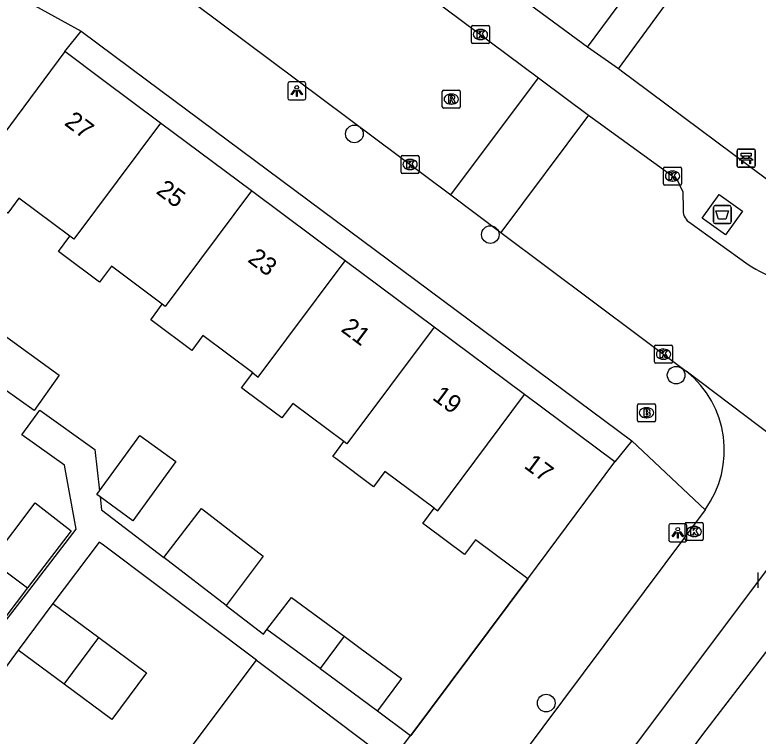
# Model space of a CAD drawing. Extents: x 160026 to 161302, y 384757 to 385701.
# Drawn here: x 160351.49 to 160392.73, y 385213.57 to 385253.6 of the extents above; entities that cross this region are included whole.
import ezdxf

# ---------------------------------------------------------------- set-up
doc = ezdxf.new("R2010")
doc.units = 0
for name, color, linetype in [('IMGEO_Afval_apart_plaats', 7, 'Continuous'), ('IMGEO_Bank', 7, 'Continuous'), ('IMGEO_Boom', 7, 'Continuous'), ('IMGEO_Brandkraan', 7, 'Continuous'), ('IMGEO_Kolk', 7, 'Continuous'), ('IMGEO_Lichtpunt', 7, 'Continuous'), ('IMGEO_Muur', 7, 'Continuous'), ('IMGEO_Pand', 7, 'Continuous'), ('IMGEO_Pand_nummerreeks', 7, 'Continuous'), ('IMGEO_Rijbaan_lokaal_gesloten', 7, 'Continuous'), ('IMGEO_Rijbaan_lokaal_open', 7, 'Continuous'), ('IMGEO_Rioolput', 7, 'Continuous'), ('IMGEO_Voetpad_gesloten', 7, 'Continuous'), ('IMGEO_Voetpad_open', 7, 'Continuous')]:
    doc.layers.add(name, color=color, linetype=linetype)

msp = doc.modelspace()

# ---------------------------------------------------------------- linework, layer by layer
at = {"layer": 'IMGEO_Afval_apart_plaats'}
for p, q in [((160390.249, 385242.11), (160390.249, 385242.91)), ((160390.249, 385242.91), (160390.249, 385242.11)), ((160390.349, 385243.01), (160391.139, 385243.01)), ((160391.139, 385243.01), (160390.349, 385243.01)), ((160391.239, 385242.91), (160391.239, 385242.11)), ((160391.239, 385242.11), (160391.239, 385242.91)), ((160391.139, 385242.01), (160390.349, 385242.01)), ((160390.349, 385242.01), (160391.139, 385242.01))]:
    msp.add_line(p, q, dxfattribs=at)
msp.add_lwpolyline([(160390.392, 385242.724), (160391.096, 385242.724), (160390.947, 385242.254), (160390.541, 385242.254), (160390.392, 385242.724)], dxfattribs=at)
for centre, start, end in [((160390.349, 385242.91), 90, 180), ((160390.349, 385242.91), 90, 180), ((160391.139, 385242.91), 0, 90), ((160391.139, 385242.91), 360, 90), ((160390.349, 385242.11), 180, 270), ((160390.349, 385242.11), 180, 270), ((160391.139, 385242.11), 270, 0), ((160391.139, 385242.11), 270, 0)]:
    msp.add_arc(centre, 0.1, start, end, dxfattribs=at)
at = {"layer": 'IMGEO_Bank'}
for p, q in [((160391.645, 385246.144), (160392.486, 385246.144)), ((160392.486, 385246.144), (160391.645, 385246.144)), ((160391.57, 385245.219), (160391.57, 385246.06)), ((160391.57, 385246.06), (160391.57, 385245.219)), ((160391.879, 385245.65), (160391.879, 385245.756)), ((160391.923, 385245.756), (160391.923, 385245.65)), ((160392.211, 385245.762), (160391.929, 385245.762)), ((160392.217, 385245.65), (160392.217, 385245.756)), ((160392.261, 385245.756), (160392.261, 385245.65)), ((160392.57, 385246.069), (160392.57, 385245.228)), ((160392.57, 385245.228), (160392.57, 385246.069)), ((160392.267, 385245.542), (160391.874, 385245.542)), ((160391.929, 385245.644), (160392.211, 385245.644)), ((160392.495, 385245.144), (160391.654, 385245.144)), ((160391.654, 385245.144), (160392.495, 385245.144))]:
    msp.add_line(p, q, dxfattribs=at)
for points in [[(160391.873, 385245.762), (160391.787, 385245.762), (160391.787, 385245.923), (160392.35, 385245.923), (160392.35, 385245.762), (160392.267, 385245.762)], [(160391.817, 385245.542), (160391.675, 385245.542), (160391.787, 385245.644), (160391.873, 385245.644)], [(160391.867, 385245.535), (160391.867, 385245.328), (160391.824, 385245.328), (160391.824, 385245.535)], [(160392.267, 385245.644), (160392.35, 385245.644), (160392.462, 385245.542), (160392.323, 385245.542)], [(160392.317, 385245.535), (160392.317, 385245.328), (160392.273, 385245.328), (160392.273, 385245.535)]]:
    msp.add_lwpolyline(points, dxfattribs=at)
for centre, radius, start, end in [((160391.648, 385246.066), 0.0779, 92.4484, 184.2845), ((160391.648, 385246.066), 0.0779, 92.4484, 184.2845), ((160392.492, 385246.066), 0.0779, 2.4484, 94.2845), ((160392.492, 385246.066), 0.0779, 2.4484, 94.2845), ((160391.872, 385245.755), 0.00671, 2.8957, 87.1043), ((160391.929, 385245.755), 0.00671, 92.8957, 177.1043), ((160392.211, 385245.755), 0.00671, 2.8957, 87.1043), ((160392.268, 385245.755), 0.00671, 92.8957, 177.1043), ((160391.817, 385245.535), 0.00671, 2.8957, 87.1043), ((160391.874, 385245.535), 0.00671, 92.8957, 177.1043), ((160391.872, 385245.651), 0.00671, 272.8957, 357.1043), ((160391.929, 385245.651), 0.00671, 182.8957, 267.1043), ((160392.211, 385245.651), 0.00671, 272.8957, 357.1043), ((160392.268, 385245.651), 0.00671, 182.8957, 267.1043), ((160392.266, 385245.535), 0.00671, 2.8957, 87.1043), ((160392.323, 385245.535), 0.00671, 92.8957, 177.1043), ((160391.648, 385245.222), 0.0779, 182.4484, 274.2845), ((160391.648, 385245.222), 0.0779, 182.4484, 274.2845), ((160392.492, 385245.222), 0.0779, 272.4484, 4.2845), ((160392.492, 385245.222), 0.0779, 272.4484, 4.2845)]:
    msp.add_arc(centre, radius, start, end, dxfattribs=at)
at = {"layer": 'IMGEO_Boom'}
for centre in [(160370.33, 385246.99), (160377.873, 385241.404), (160388.183, 385233.601), (160380.975, 385215.404)]:
    msp.add_circle(centre, 0.489, dxfattribs=at)
at = {"layer": 'IMGEO_Brandkraan'}
for p, q in [((160386.039, 385231.09), (160386.039, 385231.942)), ((160386.114, 385232.016), (160386.966, 385232.016)), ((160386.527, 385231.796), (160386.552, 385231.796)), ((160387.04, 385231.942), (160387.04, 385231.09)), ((160386.966, 385231.016), (160386.114, 385231.016)), ((160386.55, 385231.236), (160386.525, 385231.236))]:
    msp.add_line(p, q, dxfattribs=at)
for points in [[(160386.039, 385231.09), (160386.039, 385231.942)], [(160386.114, 385232.016), (160386.966, 385232.016)], [(160386.387, 385231.716), (160386.387, 385231.316), (160386.6, 385231.316)], [(160386.618, 385231.716), (160386.387, 385231.716)], [(160387.04, 385231.942), (160387.04, 385231.09)], [(160386.566, 385231.635), (160386.512, 385231.635), (160386.512, 385231.559)], [(160386.512, 385231.559), (160386.565, 385231.559)], [(160386.574, 385231.483), (160386.512, 385231.483), (160386.512, 385231.402)], [(160386.512, 385231.402), (160386.574, 385231.402)], [(160386.966, 385231.016), (160386.114, 385231.016)]]:
    msp.add_lwpolyline(points, dxfattribs=at)
for centre, radius, start, end in [((160386.116, 385231.94), 0.0765, 91.552, 178.448), ((160386.116, 385231.94), 0.0765, 91.552, 178.448), ((160386.622, 385231.571), 0.145, 59.4692, 91.5367), ((160386.647, 385231.618), 0.0922, 285.5137, 58.1501), ((160386.964, 385231.94), 0.0765, 1.552, 88.448), ((160386.964, 385231.94), 0.0765, 1.552, 88.448), ((160386.567, 385231.597), 0.0379, 267.8285, 90.9355), ((160386.575, 385231.442), 0.0404, 269.8759, 90.5077), ((160386.606, 385231.567), 0.251, 268.6676, 293.5347), ((160386.652, 385231.426), 0.105, 301.3115, 78.989), ((160386.116, 385231.092), 0.0765, 181.552, 268.448), ((160386.116, 385231.092), 0.0765, 181.552, 268.448), ((160386.964, 385231.092), 0.0765, 271.552, 358.448), ((160386.964, 385231.092), 0.0765, 271.552, 358.448)]:
    msp.add_arc(centre, radius, start, end, dxfattribs=at)
for centre, major_axis, ratio, start_param, end_param in [((160386.526, 385231.516), (-0.387, 0.002), 0.722429, 4.712389, 7.853982), ((160386.551, 385231.516), (-0.39, 0.002), 0.717154, 1.570796, 4.712389)]:
    msp.add_ellipse(centre, major_axis=major_axis, ratio=ratio, start_param=start_param, end_param=end_param, dxfattribs=at)
at = {"layer": 'IMGEO_Kolk'}
for p, q in [((160376.824, 385252.082), (160376.824, 385252.934)), ((160376.899, 385253.008), (160377.751, 385253.008)), ((160377.312, 385252.788), (160377.337, 385252.788)), ((160377.825, 385252.934), (160377.825, 385252.082)), ((160377.751, 385252.008), (160376.899, 385252.008)), ((160377.335, 385252.228), (160377.31, 385252.228)), ((160372.918, 385244.868), (160372.918, 385245.72)), ((160372.993, 385245.794), (160373.845, 385245.794)), ((160373.919, 385245.72), (160373.919, 385244.868)), ((160373.406, 385245.574), (160373.431, 385245.574)), ((160373.429, 385245.014), (160373.404, 385245.014)), ((160387.485, 385244.223), (160387.485, 385245.075)), ((160387.56, 385245.149), (160388.412, 385245.149)), ((160387.973, 385244.929), (160387.998, 385244.929)), ((160388.486, 385245.075), (160388.486, 385244.223)), ((160373.845, 385244.794), (160372.993, 385244.794)), ((160388.412, 385244.149), (160387.56, 385244.149)), ((160387.996, 385244.369), (160387.971, 385244.369)), ((160386.985, 385234.339), (160386.985, 385235.191)), ((160387.06, 385235.265), (160387.912, 385235.265)), ((160387.473, 385235.045), (160387.498, 385235.045)), ((160387.986, 385235.191), (160387.986, 385234.339)), ((160387.912, 385234.265), (160387.06, 385234.265)), ((160387.496, 385234.485), (160387.471, 385234.485)), ((160388.684, 385224.499), (160388.684, 385225.351)), ((160388.759, 385225.425), (160389.611, 385225.425)), ((160389.172, 385225.205), (160389.197, 385225.205)), ((160389.685, 385225.351), (160389.685, 385224.499)), ((160389.195, 385224.645), (160389.17, 385224.645)), ((160389.611, 385224.425), (160388.759, 385224.425)), ((160392.733, 385221.805), (160392.733, 385222.657))]:
    msp.add_line(p, q, dxfattribs=at)
for points in [[(160376.824, 385252.082), (160376.824, 385252.934)], [(160376.899, 385253.008), (160377.751, 385253.008)], [(160377.145, 385252.708), (160377.268, 385252.708), (160377.268, 385252.557), (160377.398, 385252.708), (160377.562, 385252.708), (160377.416, 385252.557), (160377.569, 385252.308), (160377.417, 385252.308), (160377.332, 385252.472), (160377.268, 385252.405), (160377.268, 385252.308), (160377.145, 385252.308), (160377.145, 385252.708)], [(160377.825, 385252.934), (160377.825, 385252.082)], [(160377.751, 385252.008), (160376.899, 385252.008)], [(160372.918, 385244.868), (160372.918, 385245.72)], [(160372.993, 385245.794), (160373.845, 385245.794)], [(160373.919, 385245.72), (160373.919, 385244.868)], [(160373.239, 385245.494), (160373.362, 385245.494), (160373.362, 385245.343), (160373.492, 385245.494), (160373.656, 385245.494), (160373.51, 385245.343), (160373.663, 385245.094), (160373.511, 385245.094), (160373.426, 385245.258), (160373.362, 385245.191), (160373.362, 385245.094), (160373.239, 385245.094), (160373.239, 385245.494)], [(160387.485, 385244.223), (160387.485, 385245.075)], [(160387.56, 385245.149), (160388.412, 385245.149)], [(160387.806, 385244.849), (160387.929, 385244.849), (160387.929, 385244.698), (160388.059, 385244.849), (160388.223, 385244.849), (160388.077, 385244.698), (160388.23, 385244.449), (160388.078, 385244.449), (160387.993, 385244.613), (160387.929, 385244.546), (160387.929, 385244.449), (160387.806, 385244.449), (160387.806, 385244.849)], [(160388.486, 385245.075), (160388.486, 385244.223)], [(160373.845, 385244.794), (160372.993, 385244.794)], [(160388.412, 385244.149), (160387.56, 385244.149)], [(160386.985, 385234.339), (160386.985, 385235.191)], [(160387.06, 385235.265), (160387.912, 385235.265)], [(160387.306, 385234.965), (160387.429, 385234.965), (160387.429, 385234.814), (160387.559, 385234.965), (160387.723, 385234.965), (160387.577, 385234.814), (160387.73, 385234.565), (160387.578, 385234.565), (160387.493, 385234.729), (160387.429, 385234.662), (160387.429, 385234.565), (160387.306, 385234.565), (160387.306, 385234.965)], [(160387.986, 385235.191), (160387.986, 385234.339)], [(160387.912, 385234.265), (160387.06, 385234.265)], [(160388.684, 385224.499), (160388.684, 385225.351)], [(160388.759, 385225.425), (160389.611, 385225.425)], [(160389.005, 385225.125), (160389.128, 385225.125), (160389.128, 385224.974), (160389.258, 385225.125), (160389.422, 385225.125), (160389.276, 385224.974), (160389.429, 385224.725), (160389.277, 385224.725), (160389.192, 385224.889), (160389.128, 385224.822), (160389.128, 385224.725), (160389.005, 385224.725), (160389.005, 385225.125)], [(160389.685, 385225.351), (160389.685, 385224.499)], [(160389.611, 385224.425), (160388.759, 385224.425)], [(160392.733, 385221.805), (160392.733, 385222.657)]]:
    msp.add_lwpolyline(points, dxfattribs=at)
for centre, start, end in [((160376.901, 385252.932), 91.552, 178.448), ((160376.901, 385252.932), 91.552, 178.448), ((160377.749, 385252.932), 1.552, 88.448), ((160377.749, 385252.932), 1.552, 88.448), ((160376.901, 385252.084), 181.552, 268.448), ((160376.901, 385252.084), 181.552, 268.448), ((160377.749, 385252.084), 271.552, 358.448), ((160377.749, 385252.084), 271.552, 358.448), ((160372.995, 385245.718), 91.552, 178.448), ((160372.995, 385245.718), 91.552, 178.448), ((160373.843, 385245.718), 1.552, 88.448), ((160373.843, 385245.718), 1.552, 88.448), ((160372.995, 385244.87), 181.552, 268.448), ((160372.995, 385244.87), 181.552, 268.448), ((160373.843, 385244.87), 271.552, 358.448), ((160373.843, 385244.87), 271.552, 358.448), ((160387.562, 385245.073), 91.552, 178.448), ((160387.562, 385245.073), 91.552, 178.448), ((160388.41, 385245.073), 1.552, 88.448), ((160388.41, 385245.073), 1.552, 88.448), ((160387.562, 385244.225), 181.552, 268.448), ((160387.562, 385244.225), 181.552, 268.448), ((160388.41, 385244.225), 271.552, 358.448), ((160388.41, 385244.225), 271.552, 358.448), ((160387.062, 385235.189), 91.552, 178.448), ((160387.062, 385235.189), 91.552, 178.448), ((160387.91, 385235.189), 1.552, 88.448), ((160387.91, 385235.189), 1.552, 88.448), ((160387.062, 385234.341), 181.552, 268.448), ((160387.062, 385234.341), 181.552, 268.448), ((160387.91, 385234.341), 271.552, 358.448), ((160387.91, 385234.341), 271.552, 358.448), ((160388.761, 385225.349), 91.552, 178.448), ((160388.761, 385225.349), 91.552, 178.448), ((160389.609, 385225.349), 1.552, 88.448), ((160389.609, 385225.349), 1.552, 88.448), ((160388.761, 385224.501), 181.552, 268.448), ((160388.761, 385224.501), 181.552, 268.448), ((160389.609, 385224.501), 271.552, 358.448), ((160389.609, 385224.501), 271.552, 358.448)]:
    msp.add_arc(centre, 0.0765, start, end, dxfattribs=at)
for centre, major_axis, ratio, start_param, end_param in [((160377.311, 385252.508), (-0.387, 0.002), 0.722429, 4.712389, 7.853982), ((160377.336, 385252.508), (-0.39, 0.002), 0.717154, 1.570796, 4.712389), ((160373.405, 385245.294), (-0.387, 0.002), 0.722429, 4.712389, 7.853982), ((160373.43, 385245.294), (-0.39, 0.002), 0.717154, 1.570796, 4.712389), ((160387.972, 385244.649), (-0.387, 0.002), 0.722429, 4.712389, 7.853982), ((160387.997, 385244.649), (-0.39, 0.002), 0.717154, 1.570796, 4.712389), ((160387.472, 385234.765), (-0.387, 0.002), 0.722429, 4.712389, 7.853982), ((160387.497, 385234.765), (-0.39, 0.002), 0.717154, 1.570796, 4.712389), ((160389.171, 385224.925), (-0.387, 0.002), 0.722429, 4.712389, 7.853982), ((160389.196, 385224.925), (-0.39, 0.002), 0.717154, 1.570796, 4.712389)]:
    msp.add_ellipse(centre, major_axis=major_axis, ratio=ratio, start_param=start_param, end_param=end_param, dxfattribs=at)
at = {"layer": 'IMGEO_Lichtpunt'}
for p, q in [((160367.538, 385249.872), (160366.73, 385249.872)), ((160367.538, 385249.872), (160366.73, 385249.872)), ((160366.636, 385249.777), (160366.636, 385248.97)), ((160366.636, 385249.777), (160366.636, 385248.97)), ((160367.632, 385248.97), (160367.632, 385249.777)), ((160367.632, 385248.97), (160367.632, 385249.777)), ((160366.73, 385248.876), (160367.538, 385248.876)), ((160366.73, 385248.876), (160367.538, 385248.876)), ((160387.776, 385225.258), (160387.776, 385224.451)), ((160387.776, 385225.258), (160387.776, 385224.451)), ((160388.678, 385225.353), (160387.87, 385225.353)), ((160388.678, 385225.353), (160387.87, 385225.353)), ((160388.772, 385224.451), (160388.772, 385225.258)), ((160388.772, 385224.451), (160388.772, 385225.258)), ((160387.87, 385224.357), (160388.678, 385224.357)), ((160387.87, 385224.357), (160388.678, 385224.357))]:
    msp.add_line(p, q, dxfattribs=at)
for points in [[(160367.01, 385249.441), (160367.049, 385249.413), (160366.861, 385249.151), (160366.823, 385249.178), (160367.01, 385249.441)], [(160367.112, 385249.393), (160367.159, 385249.393), (160367.159, 385249.071), (160367.112, 385249.071), (160367.112, 385249.393)], [(160367.222, 385249.413), (160367.26, 385249.44), (160367.447, 385249.178), (160367.408, 385249.15), (160367.222, 385249.413)], [(160388.15, 385224.922), (160388.189, 385224.894), (160388.001, 385224.632), (160387.963, 385224.659), (160388.15, 385224.922)], [(160388.252, 385224.874), (160388.299, 385224.874), (160388.299, 385224.552), (160388.252, 385224.552), (160388.252, 385224.874)], [(160388.362, 385224.894), (160388.4, 385224.921), (160388.587, 385224.659), (160388.548, 385224.631), (160388.362, 385224.894)]]:
    msp.add_lwpolyline(points, dxfattribs=at)
for centre in [(160367.135, 385249.575), (160388.275, 385225.056)]:
    msp.add_circle(centre, 0.0994, dxfattribs=at)
for centre, start, end in [((160366.73, 385249.777), 90, 180), ((160366.73, 385249.777), 90, 180), ((160367.538, 385249.777), 0, 90), ((160367.538, 385249.777), 0, 90), ((160366.73, 385248.97), 180, 270), ((160366.73, 385248.97), 180, 270), ((160367.538, 385248.97), 270, 0), ((160367.538, 385248.97), 270, 360), ((160387.87, 385225.258), 90, 180), ((160387.87, 385225.258), 90, 180), ((160388.678, 385225.258), 0, 90), ((160388.678, 385225.258), 0, 90), ((160387.87, 385224.451), 180, 270), ((160387.87, 385224.451), 180, 270), ((160388.678, 385224.451), 270, 0), ((160388.678, 385224.451), 270, 360)]:
    msp.add_arc(centre, 0.0946, start, end, dxfattribs=at)
at = {"layer": 'IMGEO_Muur'}
msp.add_lwpolyline([(160379.946, 385222.303), (160373.461, 385213.61)], dxfattribs=at)
at = {"layer": 'IMGEO_Pand'}
for points in [[(160354.267, 385251.555), (160353.107, 385250), (160350.494, 385246.499)], [(160359.572, 385247.596), (160356.351, 385250), (160354.267, 385251.555)], [(160359.572, 385247.596), (160354.76, 385241.145), (160354.534, 385241.314)], [(160364.619, 385243.831), (160359.572, 385247.596)], [(160354.534, 385241.314), (160351.715, 385243.417), (160351.096, 385242.587), (160349.055, 385244.075)], [(160364.619, 385243.831), (160359.835, 385237.418), (160359.674, 385237.538)], [(160369.815, 385239.953), (160364.619, 385243.831)], [(160359.674, 385237.538), (160356.852, 385239.644), (160356.194, 385238.762), (160354.131, 385240.302), (160353.905, 385240.47), (160354.534, 385241.314)], [(160364.687, 385233.733), (160365.001, 385233.499), (160369.815, 385239.953)], [(160374.753, 385236.269), (160369.815, 385239.953)], [(160364.687, 385233.733), (160361.924, 385235.795), (160361.312, 385234.974), (160359.192, 385236.557), (160359.031, 385236.677), (160359.674, 385237.538)], [(160374.753, 385236.269), (160369.918, 385229.789), (160369.746, 385229.917)], [(160379.773, 385232.523), (160374.753, 385236.269)], [(160352.566, 385231.639), (160349.217, 385234.008), (160350.234, 385235.447), (160350.63, 385236.005), (160353.95, 385233.596), (160352.566, 385231.639)], [(160369.746, 385229.917), (160366.909, 385232.033), (160366.308, 385231.228), (160364.38, 385232.667), (160364.066, 385232.901), (160364.687, 385233.733)], [(160374.764, 385226.212), (160374.957, 385226.068), (160379.773, 385232.523)], [(160384.783, 385228.785), (160379.773, 385232.523)], [(160356.185, 385227.185), (160358.428, 385230.261), (160360.426, 385228.803), (160358.035, 385225.524), (160356.223, 385226.844)], [(160374.764, 385226.212), (160372.028, 385228.254), (160371.396, 385227.408), (160369.306, 385228.968), (160369.134, 385229.096), (160369.746, 385229.917)], [(160379.946, 385222.303), (160384.783, 385228.785)], [(160356.223, 385226.844), (160356.036, 385226.981), (160356.185, 385227.185)], [(160350.173, 385223.306), (160352.62, 385226.513), (160354.619, 385224.965), (160352.202, 385221.799)], [(160359.757, 385223.475), (160361.842, 385226.196), (160365.275, 385223.565), (160363.225, 385220.818)], [(160379.946, 385222.303), (160377.044, 385224.469), (160376.432, 385223.649), (160374.325, 385225.221), (160374.132, 385225.365), (160374.764, 385226.212)], [(160352.202, 385221.799), (160349.716, 385218.543), (160347.116, 385220.473), (160349.558, 385223.762), (160350.173, 385223.306)], [(160363.225, 385220.818), (160359.757, 385223.475)], [(160350.173, 385223.306), (160352.202, 385221.799)], [(160353.604, 385220.933), (160351.681, 385218.338)], [(160353.604, 385220.933), (160356.156, 385219.042)], [(160365.481, 385219.488), (160366.842, 385221.265), (160369.766, 385219.111)], [(160368.428, 385217.317), (160365.481, 385219.488)], [(160356.156, 385219.042), (160358.797, 385217.084), (160356.874, 385214.49), (160354.232, 385216.447)], [(160354.232, 385216.447), (160356.156, 385219.042)], [(160369.766, 385219.111), (160368.428, 385217.317)], [(160369.766, 385219.111), (160370.658, 385218.454), (160372.936, 385216.776), (160371.609, 385214.974)], [(160354.232, 385216.447), (160351.681, 385218.338)], [(160361.059, 385212.654), (160364.899, 385217.78)], [(160364.899, 385217.78), (160367.434, 385215.874), (160371.43, 385212.869)], [(160368.428, 385217.317), (160369.331, 385216.652), (160371.609, 385214.974)]]:
    msp.add_lwpolyline(points, dxfattribs=at)
at = {"layer": 'IMGEO_Rijbaan_lokaal_gesloten'}
for points in [[(160316.228, 385298.079), (160333.903, 385284.92), (160353.887, 385269.963), (160380.549, 385250.106)], [(160357.361, 385257.313), (160367.132, 385250), (160375.681, 385243.601)], [(160383.33, 385248.034), (160387.482, 385245.014), (160388.218, 385244.48), (160388.547, 385243.785), (160388.572, 385242.838)], [(160388.882, 385242.103), (160392.177, 385239.749)], [(160378.457, 385241.523), (160388.748, 385233.82)], [(160401.759, 385223.985), (160388.748, 385233.82)]]:
    msp.add_lwpolyline(points, dxfattribs=at)
for centre, radius, start, end in [((160389.389, 385242.75), 0.822, 173.8355, 231.9015), ((160395.912, 385245.291), 6.683, 236.0218, 269.7966)]:
    msp.add_arc(centre, radius, start, end, dxfattribs=at)
at = {"layer": 'IMGEO_Rijbaan_lokaal_open'}
for points in [[(160375.681, 385243.601), (160380.549, 385250.106)], [(160380.549, 385250.106), (160380.691, 385250), (160383.33, 385248.034)], [(160383.33, 385248.034), (160378.457, 385241.523)], [(160375.681, 385243.601), (160378.457, 385241.523)], [(160389.791, 385226.135), (160376.256, 385207.995), (160364.435, 385192.191), (160353.385, 385177.257), (160342.6, 385162.805), (160333.448, 385150.481), (160328.079, 385143.273)], [(160382.334, 385208.244), (160383.113, 385209.309), (160388.76, 385216.851), (160393.378, 385222.996)]]:
    msp.add_lwpolyline(points, dxfattribs=at)
msp.add_arc((160385.242, 385229.431), 5.618, 324.0777, 51.3801, dxfattribs=at)
at = {"layer": 'IMGEO_Rioolput'}
for p, q in [((160375.283, 385249.421), (160376.135, 385249.421)), ((160375.208, 385248.495), (160375.208, 385249.347)), ((160375.696, 385249.201), (160375.721, 385249.201)), ((160376.209, 385249.347), (160376.209, 385248.495)), ((160375.719, 385248.641), (160375.694, 385248.641)), ((160376.135, 385248.421), (160375.283, 385248.421))]:
    msp.add_line(p, q, dxfattribs=at)
for points in [[(160375.283, 385249.421), (160376.135, 385249.421)], [(160375.208, 385248.495), (160375.208, 385249.347)], [(160375.797, 385249.119), (160375.545, 385249.121), (160375.545, 385248.721)], [(160375.723, 385249.04), (160375.669, 385249.04), (160375.669, 385248.959)], [(160376.209, 385249.347), (160376.209, 385248.495)], [(160375.545, 385248.721), (160375.669, 385248.721), (160375.669, 385248.883), (160375.68, 385248.883)], [(160375.669, 385248.959), (160375.721, 385248.959)], [(160375.727, 385248.854), (160375.798, 385248.721), (160375.938, 385248.721), (160375.873, 385248.847)], [(160376.135, 385248.421), (160375.283, 385248.421)]]:
    msp.add_lwpolyline(points, dxfattribs=at)
for centre, radius, start, end in [((160375.285, 385249.345), 0.0765, 91.552, 178.448), ((160375.285, 385249.345), 0.0765, 91.552, 178.448), ((160376.133, 385249.345), 0.0765, 1.552, 88.448), ((160376.133, 385249.345), 0.0765, 1.552, 88.448), ((160375.729, 385248.944), 0.0964, 77.0061, 93.1865), ((160375.743, 385249.001), 0.0378, 276.6634, 79.6772), ((160375.796, 385249.009), 0.109, 350.3612, 89.416), ((160375.794, 385249.009), 0.112, 277.5842, 350.9817), ((160375.679, 385248.83), 0.0533, 26.0293, 88.6989), ((160375.705, 385249.148), 0.19, 274.7715, 282.9687), ((160375.778, 385248.794), 0.108, 29.5134, 73.7905), ((160375.285, 385248.497), 0.0765, 181.552, 268.448), ((160375.285, 385248.497), 0.0765, 181.552, 268.448), ((160376.133, 385248.497), 0.0765, 271.552, 358.448), ((160376.133, 385248.497), 0.0765, 271.552, 358.448)]:
    msp.add_arc(centre, radius, start, end, dxfattribs=at)
for centre, major_axis, ratio, start_param, end_param in [((160375.695, 385248.921), (-0.387, 0.002), 0.722429, 4.712389, 7.853982), ((160375.72, 385248.921), (-0.39, 0.002), 0.717154, 1.570796, 4.712389)]:
    msp.add_ellipse(centre, major_axis=major_axis, ratio=ratio, start_param=start_param, end_param=end_param, dxfattribs=at)
at = {"layer": 'IMGEO_Voetpad_gesloten'}
msp.add_lwpolyline([(160390.57, 385243.629), (160391.858, 385242.711), (160390.917, 385241.39), (160389.629, 385242.308), (160390.57, 385243.629)], dxfattribs=at)
at = {"layer": 'IMGEO_Voetpad_open'}
for points in [[(160384.978, 385250.606), (160392.388, 385260.712)], [(160383.271, 385251.807), (160387.145, 385257.063)], [(160349.029, 385256.073), (160355.176, 385252.701)], [(160383.271, 385251.807), (160377.817, 385255.835)], [(160354.267, 385251.555), (160355.176, 385252.701)], [(160355.176, 385252.701), (160358.802, 385250), (160385.717, 385229.954)], [(160384.978, 385250.606), (160383.271, 385251.807)], [(160394.139, 385243.772), (160385.791, 385250), (160385.233, 385250.416), (160384.978, 385250.606)], [(160340.125, 385222.948), (160348.455, 385216.731), (160348.689, 385217.034), (160352.316, 385221.715), (160354.9, 385225.049), (160354.239, 385228.601), (160351.887, 385230.285), (160352.872, 385231.659), (160355.928, 385229.47), (160356.185, 385227.185)], [(160385.717, 385229.954), (160384.783, 385228.785)], [(160385.717, 385229.954), (160389.791, 385226.135)], [(160356.223, 385226.844), (160356.305, 385226.12), (160359.757, 385223.475)], [(160364.899, 385217.78), (160356.402, 385224.169), (160356.17, 385224.343), (160353.604, 385220.933)], [(160373.453, 385213.599), (160373.461, 385213.61), (160379.946, 385222.303)], [(160363.225, 385220.818), (160365.288, 385219.237), (160365.481, 385219.488)], [(160394.69, 385220.175), (160394.309, 385219.721), (160389.638, 385213.652), (160384.604, 385206.829), (160391.713, 385201.212), (160391.988, 385201.554), (160403.665, 385216.056)], [(160351.681, 385218.338), (160346.193, 385210.873)], [(160371.609, 385214.974), (160373.453, 385213.599)], [(160372.389, 385212.172), (160373.453, 385213.599)]]:
    msp.add_lwpolyline(points, dxfattribs=at)

# ---------------------------------------------------------------- texts
at = {"layer": 'IMGEO_Pand_nummerreeks'}
for s, p in [('27', (160354.187, 385247.523)), ('25', (160359.273, 385243.728)), ('23', (160364.359, 385239.933)), ('21', (160369.535, 385236.071)), ('19', (160374.604, 385232.289)), ('17', (160379.69, 385228.494))]:
    msp.add_text(s, height=1, rotation=323.2734, dxfattribs=at).set_placement(p)

doc.saveas('drawing.dxf')
